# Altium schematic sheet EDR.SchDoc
size A; SheetNumber: 1; SheetTotal: 1
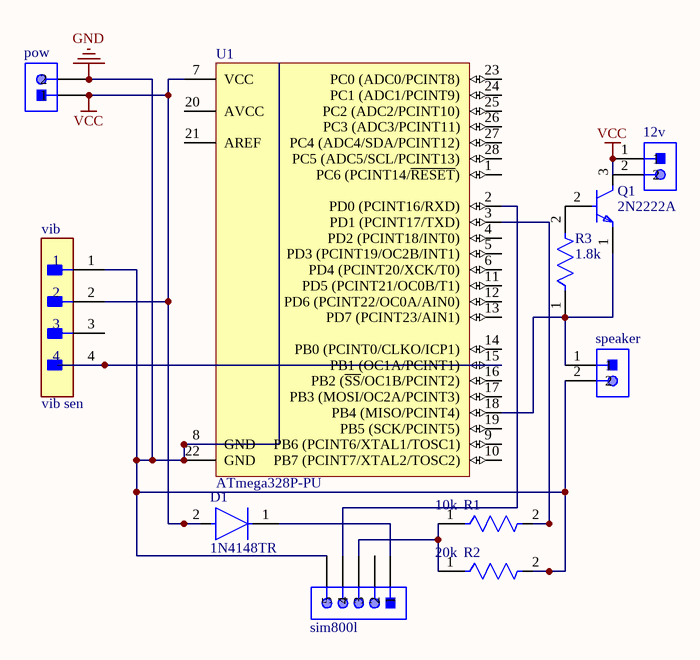
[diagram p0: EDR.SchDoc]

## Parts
12v  (no value)  [61300211121]
D1  1N4148TR  [FP-017AG-MFG]
pow  (no value)  [61300211121]
Q1  2N2222A  [FP-2N2222A-MFG]
R1  Resistance: 10k  [FP-SFR25-MFG]
R2  Resistance: 20k  [FP-SFR25-MFG]
R3  Resistance: 1.8k  [FP-SFR25-MFG]
sim800l  (no value)  [61900511121]
speaker  (no value)  [61300211121]
U1  ATmega328P-PU  [28P3]
vib  vib sen  [FP-110990030-MFG]

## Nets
GND: pow.2 R2.2 sim800l.5 speaker.2 U1.8(GND) U1.22(GND) vib.1
VCC: 12v.1 12v.2 D1.2(A) pow.1 Q1.3(C) U1.7(VCC) vib.2
NetD1_1: D1.1(C) sim800l.1
NetQ1_1: Q1.1(E) R3.1 speaker.1 U1.18(PB4_(MISO/PCINT4))
NetQ1_2: Q1.2(B) R3.2
NetR1_1: R1.1 R2.1 sim800l.3
NetR1_2: R1.2 U1.3(PD1_(PCINT17/TXD))
Netsim800l_4: sim800l.4 U1.2(PD0_(PCINT16/RXD))
NetU1_15: U1.15(PB1_(OC1A/PCINT1)) vib.4

Not connected (* = marked no-connect by the designer): sim800l 2; U1 1(PC6_(PCINT14/~{RESET})) 4(PD2_(PCINT18/INT0)) 5(PD3_(PCINT19/OC2B/INT1)) 6(PD4_(PCINT20/XCK/T0)) 9(PB6_(PCINT6/XTAL1/TOSC1)) 10(PB7_(PCINT7/XTAL2/TOSC2)) 11(PD5_(PCINT21/OC0B/T1)) 12(PD6_(PCINT22/OC0A/AIN0)) 13(PD7_(PCINT23/AIN1)) 14(PB0_(PCINT0/CLKO/ICP1)) 16(PB2_(~{SS}/OC1B/PCINT2)) 17(PB3_(MOSI/OC2A/PCINT3)) 19(PB5_(SCK/PCINT5)) 20(AVCC) 21(AREF) 23(PC0_(ADC0/PCINT8)) 24(PC1_(ADC1/PCINT9)) 25(PC2_(ADC2/PCINT10)) 26(PC3_(ADC3/PCINT11)) 27(PC4_(ADC4/SDA/PCINT12)) 28(PC5_(ADC5/SCL/PCINT13)); vib 3

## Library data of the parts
12v pow speaker = CMP-1712-00002-4: THT Vertical Pin Header WR-PHD, Pitch 2.54 mm, Single Row, 2 pins; Manufacturer: Wurth Elektronik; Rated Current: 3A; Gender: Male; Withstanding Voltage: 500VAC; Working Voltage: 250VAC; Pitch: 2.54mm; Contact Resistance: 20mOhm; Pin Number: 2
D1 = CMP-07163-000030-1: DIODE GEN PURP 100V 200MA DO35; Manufacturer: ON Semiconductor; Peak Reverse Current: 5uA; Value: 4pF; Max Junction Temp: +175°C; Max Surge Forward Current: 1A
Q1 = CMP-50385-000001-1: T-NPN SI- AUDIO VHF AMP; Max Power Dissipation: 1.2W; Collector Emitter Breakdown Voltage: 40V; Transition Frequency: 300MHz; Polarity: NPN
R1-R3 = CMP-02408-000013-1: RES 0 OHM JUMPER MF; Lead Diameter: 0.58mm
sim800l = CMP-1502-00587-1: Male Locking Header WR-WTB, THT, Vertical, pitch 2.54 mm, 1 x 5 position; Manufacturer: Wurth Elektronik; Pitch: 2.54mm; Contact Resistance: 20mOhm; Position: 1x5; Working Voltage: 250VAC
U1 = CMP-0095-00013-2: 8-bit AVR Microcontroller, 32KB Flash, 1KB EEPROM, 2KB SRAM, 28-pin PDIP, Industrial Grade (-40°C to 85°C)
vib = CMP-139044-000001-1: GROVE 2MM 4PIN VERT CONN 10PCS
